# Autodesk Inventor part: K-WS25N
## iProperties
Created: 2009-07
Part Number: K-WS25N
Document SubType Name: Modeling
Designer: TB
Mass: 64.8432 g
Surface Area: 168.018 cm^2
Volume: 64.8432 cm^3
Density: 1 g/cm^3
Author: TB
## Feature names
1. Hole1
